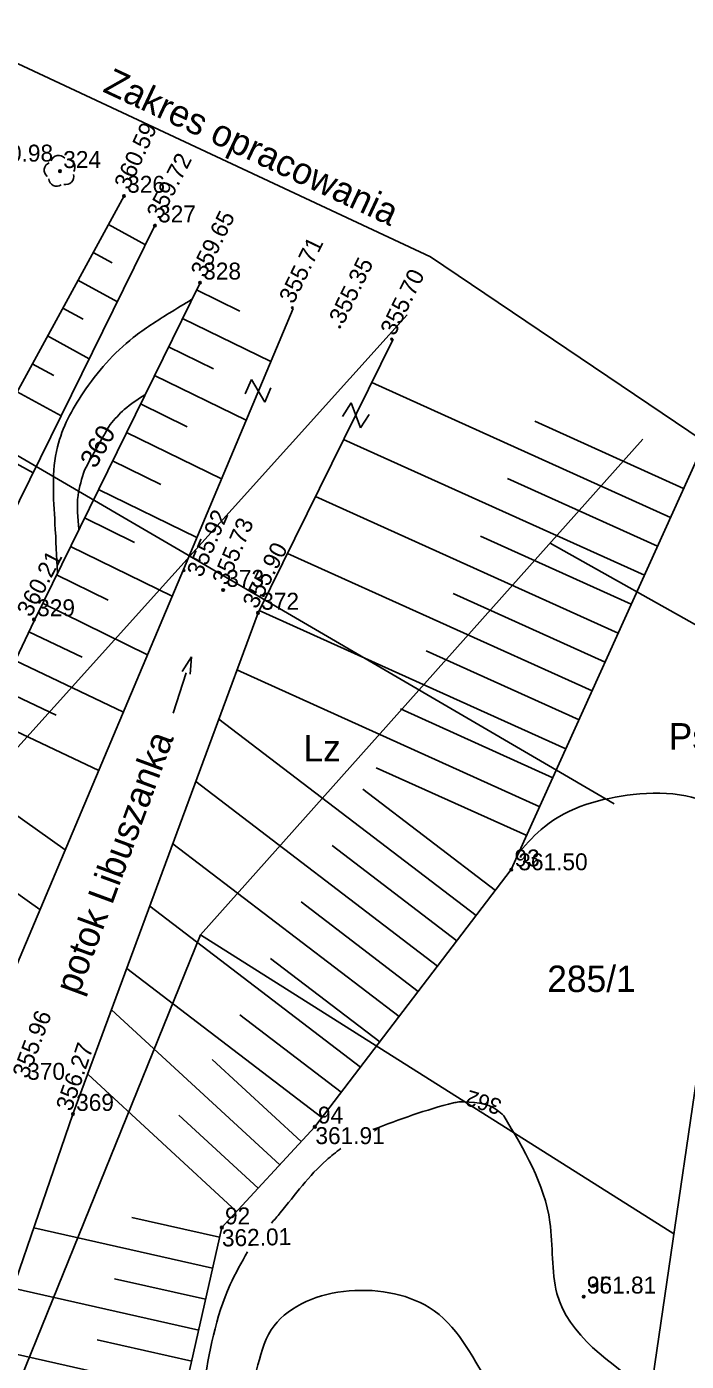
# Model space of a CAD drawing. Extents: x 4635329 to 4651863, y 5356628 to 5367582.
# Drawn here: x 4651765.3 to 4651796.5, y 5357153.9 to 5357217 of the extents above; entities that cross this region are included whole.
import ezdxf

# ---------------------------------------------------------------- set-up
doc = ezdxf.new("R2010")
doc.units = 0
for name, color, linetype in [('Level 1', 7, 'Continuous'), ('Level 12', 7, 'Continuous'), ('Level 2', 7, 'Continuous'), ('Level 4', 7, 'Continuous'), ('Level 44', 7, 'Continuous'), ('Level 45', 7, 'Continuous'), ('Level 46', 7, 'Continuous'), ('Level 47', 7, 'Continuous'), ('Level 48', 7, 'Continuous'), ('Level 5', 7, 'Continuous'), ('Level 50', 7, 'Continuous'), ('Level 51', 7, 'Continuous'), ('Level 53', 7, 'Continuous'), ('Level 55', 7, 'Continuous'), ('Level 6', 7, 'Continuous'), ('Level 63', 7, 'Continuous')]:
    doc.layers.add(name, color=color, linetype=linetype)

msp = doc.modelspace()

# ---------------------------------------------------------------- linework, layer by layer
at = {"layer": 'Level 1'}
for p, q in [((4651784.412, 5357206.105), (4651748.153, 5357223.087)), ((4651801.01, 5357194.891), (4651784.412, 5357206.105)), ((4651790.97, 5357126.195), (4651801.01, 5357194.891))]:
    msp.add_line(p, q, dxfattribs=at)
at = {"layer": 'Level 2'}
msp.add_line((4651793.081, 5357180.253), (4651732.387, 5357215.712), dxfattribs=at)
at = {"layer": 'Level 4'}
for p, q in [((4651783.305, 5357203.355), (4651763.487, 5357181.344)), ((4651773.552, 5357174.065), (4651794.437, 5357197.482)), ((4651790.062, 5357192.577), (4651799.866, 5357187.065)), ((4651762.032, 5357145.618), (4651773.552, 5357174.065)), ((4651773.552, 5357174.065), (4651795.903, 5357159.948))]:
    msp.add_line(p, q, dxfattribs=at)
at = {"layer": 'Level 44'}
for centre in [(4651766.92, 5357210.15), (4651769.94, 5357208.98), (4651771.4, 5357207.58), (4651773.53, 5357204.88), (4651777.887, 5357203.699), (4651780.126, 5357202.792), (4651782.577, 5357202.216), (4651772.775, 5357191.283), (4651774.62, 5357190.36), (4651765.69, 5357188.97), (4651776.27, 5357189.28), (4651788.23, 5357177.15), (4651767.53, 5357165.6), (4651778.95, 5357165), (4651774.56, 5357160.24), (4651791.65, 5357156.97)]:
    msp.add_circle(centre, 0.04, dxfattribs=at)
at = {"layer": 'Level 46'}
for points in [[(4651766.8, 5357191.171), (4651766.68, 5357193.493), (4651766.801, 5357197.132), (4651768.014, 5357199.68), (4651770.379, 5357202.288), (4651772.076, 5357203.44), (4651773.145, 5357204.096)], [(4651770.927, 5357199.578), (4651769.954, 5357198.891), (4651769.289, 5357198.185)], [(4651769.289, 5357198.185), (4651768.681, 5357197.132), (4651768.074, 5357196.024)], [(4651768.074, 5357196.024), (4651767.771, 5357194.827), (4651767.81, 5357193.228)], [(4651788.609, 5357177.988), (4651789.796, 5357179.176), (4651793.983, 5357180.694), (4651796.471, 5357180.633), (4651798.656, 5357180.026), (4651798.832, 5357179.987)], [(4651785.749, 5357166.181), (4651785.506, 5357166.125), (4651781.687, 5357164.864)], [(4651787.87, 5357165.517), (4651787.567, 5357165.791), (4651785.749, 5357166.181)], [(4651794.813, 5357152.488), (4651790.386, 5357157.128), (4651790.053, 5357160.494), (4651787.87, 5357165.517)], [(4651780.184, 5357163.975), (4651779.503, 5357163.426), (4651777.32, 5357160.939), (4651776.898, 5357160.44)], [(4651775.778, 5357159.098), (4651774.955, 5357157.543), (4651773.682, 5357152.641)], [(4651767.905, 5357132.82), (4651768.751, 5357133.654), (4651771.479, 5357136.02), (4651773.238, 5357137.142), (4651775.928, 5357140.766), (4651776.686, 5357143.374), (4651776.959, 5357145.861), (4651775.928, 5357148.651), (4651775.746, 5357151.41), (4651776.201, 5357153.503), (4651776.895, 5357155.4), (4651784.353, 5357156.461), (4651787.142, 5357152.883), (4651788.991, 5357150.517), (4651791.083, 5357149.092), (4651794.095, 5357147.575)]]:
    msp.add_spline(points, degree=3, dxfattribs=at)
at = {"layer": 'Level 48'}
for p, q in [((4651769.204, 5357207.631), (4651770.954, 5357206.675)), ((4651768.485, 5357206.314), (4651769.388, 5357205.821)), ((4651767.767, 5357204.997), (4651769.627, 5357203.982)), ((4651773.365, 5357204.543), (4651775.409, 5357203.539)), ((4651767.048, 5357203.681), (4651768.006, 5357203.158)), ((4651772.704, 5357203.196), (4651776.872, 5357201.15)), ((4651766.33, 5357202.364), (4651768.3, 5357201.289)), ((4651772.042, 5357201.85), (4651774.167, 5357200.807)), ((4651765.611, 5357201.047), (4651766.624, 5357200.495)), ((4651771.381, 5357200.503), (4651775.71, 5357198.378)), ((4651764.892, 5357199.73), (4651766.973, 5357198.595)), ((4651795.75, 5357193.794), (4651781.638, 5357200.17)), ((4651770.72, 5357199.157), (4651772.925, 5357198.075)), ((4651796.367, 5357195.161), (4651789.334, 5357198.339)), ((4651770.059, 5357197.81), (4651774.548, 5357195.607)), ((4651794.515, 5357191.06), (4651780.311, 5357197.477)), ((4651763.455, 5357197.097), (4651765.645, 5357195.902)), ((4651769.398, 5357196.464), (4651771.683, 5357195.343)), ((4651795.132, 5357192.427), (4651788.053, 5357195.625)), ((4651768.737, 5357195.117), (4651773.386, 5357192.836)), ((4651793.279, 5357188.326), (4651778.984, 5357194.785)), ((4651768.076, 5357193.771), (4651770.44, 5357192.61)), ((4651793.897, 5357189.693), (4651786.772, 5357192.912)), ((4651767.415, 5357192.424), (4651772.221, 5357190.065)), ((4651792.044, 5357185.592), (4651777.657, 5357192.093)), ((4651766.754, 5357191.078), (4651769.195, 5357189.88)), ((4651766.093, 5357189.732), (4651771.052, 5357187.297)), ((4651792.662, 5357186.959), (4651785.491, 5357190.199)), ((4651790.809, 5357182.858), (4651776.33, 5357189.4)), ((4651765.439, 5357188.382), (4651767.967, 5357187.18)), ((4651791.427, 5357184.225), (4651784.21, 5357187.486)), ((4651764.795, 5357187.027), (4651769.912, 5357184.596)), ((4651789.574, 5357180.124), (4651775.275, 5357186.585)), ((4651764.152, 5357185.672), (4651766.74, 5357184.442)), ((4651790.191, 5357181.491), (4651782.994, 5357184.743)), ((4651763.508, 5357184.317), (4651768.744, 5357181.829)), ((4651786.569, 5357174.976), (4651774.416, 5357184.258)), ((4651761.916, 5357181.785), (4651767.165, 5357178.088)), ((4651788.956, 5357178.758), (4651781.855, 5357181.966)), ((4651784.748, 5357172.592), (4651773.329, 5357181.313)), ((4651787.48, 5357176.168), (4651781.22, 5357180.949)), ((4651760.189, 5357179.333), (4651765.971, 5357175.26)), ((4651782.927, 5357170.207), (4651772.243, 5357178.368)), ((4651785.659, 5357173.784), (4651779.766, 5357178.285)), ((4651781.106, 5357167.823), (4651771.156, 5357175.423)), ((4651783.838, 5357171.399), (4651778.312, 5357175.62)), ((4651782.017, 5357169.015), (4651776.858, 5357172.956)), ((4651779.285, 5357165.439), (4651770.069, 5357172.479)), ((4651777.291, 5357163.201), (4651769.348, 5357170.526)), ((4651780.196, 5357166.631), (4651775.404, 5357170.291)), ((4651778.308, 5357164.304), (4651774.109, 5357168.176)), ((4651775.257, 5357160.996), (4651768.225, 5357167.481)), ((4651776.274, 5357162.098), (4651772.53, 5357165.551)), ((4651774.456, 5357159.779), (4651770.313, 5357160.713)), ((4651774.126, 5357158.316), (4651765.678, 5357160.22)), ((4651773.796, 5357156.853), (4651769.492, 5357157.823)), ((4651773.467, 5357155.39), (4651764.696, 5357157.367)), ((4651773.137, 5357153.926), (4651768.671, 5357154.933)), ((4651772.807, 5357152.463), (4651763.714, 5357154.513))]:
    msp.add_line(p, q, dxfattribs=at)
for points in [[(4651756.27, 5357183.93), (4651769.94, 5357208.98)], [(4651771.4, 5357207.58), (4651762.54, 5357189.6), (4651756.27, 5357183.93)], [(4651742.61, 5357155.07), (4651748.7, 5357162.32), (4651754.89, 5357171.81), (4651763.11, 5357183.48), (4651765.69, 5357188.91), (4651773.53, 5357204.88)], [(4651788.23, 5357177.15), (4651796.985, 5357196.528)], [(4651788.23, 5357177.15), (4651778.95, 5357165), (4651774.56, 5357160.24), (4651772.52, 5357151.19), (4651770.34, 5357137.07), (4651766.1, 5357132.52), (4651760.1, 5357122.43), (4651755.24, 5357116.54), (4651754.43, 5357111.05), (4651754.06, 5357101.72), (4651764.92, 5357096.97)]]:
    msp.add_lwpolyline(points, dxfattribs=at)
at = {"layer": 'Level 50'}
for p, q in [((4651772.754, 5357191.33), (4651777.929, 5357203.669)), ((4651776.27, 5357189.28), (4651782.647, 5357202.217)), ((4651772.754, 5357191.33), (4651762.59, 5357167.25)), ((4651767.53, 5357165.6), (4651776.27, 5357189.28)), ((4651772.689, 5357186.507), (4651773.129, 5357187.205)), ((4651773.129, 5357187.205), (4651773.069, 5357186.382)), ((4651772.254, 5357184.545), (4651772.879, 5357186.445)), ((4651760.04, 5357143.84), (4651767.53, 5357165.6))]:
    msp.add_line(p, q, dxfattribs=at)
at = {"layer": 'Level 53'}
for p, q in [((4651775.961, 5357200.312), (4651775.666, 5357199.623)), ((4651776.585, 5357199.229), (4651775.961, 5357200.312)), ((4651776.881, 5357199.918), (4651776.585, 5357199.229)), ((4651780.669, 5357199.198), (4651780.265, 5357198.565)), ((4651781.109, 5357198.028), (4651780.669, 5357199.198)), ((4651781.512, 5357198.66), (4651781.109, 5357198.028))]:
    msp.add_line(p, q, dxfattribs=at)
at = {"layer": 'Level 55'}
msp.add_circle((4651766.92, 5357210.15), 0.045, dxfattribs=at)
for centre, start, end in [((4651766.549, 5357210.2), 112.43885, 232.09024), ((4651766.853, 5357210.519), 40.34881, 160.13059), ((4651767.25, 5357210.328), 328.34804, 88.13199), ((4651767.191, 5357209.891), 256.39056, 16.04195), ((4651766.757, 5357209.812), 184.38753, 304.09327)]:
    msp.add_arc(centre, 0.375, start, end, dxfattribs=at)
at = {"layer": 'Level 63'}
for centre in [(4651766.92, 5357210.15), (4651769.94, 5357208.98), (4651771.4, 5357207.58), (4651773.53, 5357204.88), (4651774.62, 5357190.36), (4651765.69, 5357188.97), (4651776.27, 5357189.28), (4651788.23, 5357177.15), (4651767.53, 5357165.6), (4651778.95, 5357165), (4651774.56, 5357160.24), (4651791.65, 5357156.97)]:
    msp.add_circle(centre, 0.06, dxfattribs=at)

# ---------------------------------------------------------------- texts
at = {"layer": 'Level 12'}
for s, p in [('Ps', (4651795.66, 5357182.821)), ('Lz', (4651778.413, 5357182.261))]:
    msp.add_text(s, height=1.25, dxfattribs=at).set_placement(p)
at = {"layer": 'Level 45'}
for s, rotation, p in [('360.59', 65.61012, (4651770.168, 5357209.228)), ('359.72', 62.71454, (4651771.673, 5357207.822)), ('359.65', 63.95047, (4651773.765, 5357205.078)), ('355.71', 63.95047, (4651777.94, 5357203.837)), ('355.35', 63.95047, (4651780.3, 5357202.869)), ('355.70', 63.95047, (4651782.721, 5357202.324)), ('355.92', 66.98682, (4651773.609, 5357190.916)), ('355.73', 66.98682, (4651774.804, 5357190.537)), ('355.90', 62.92249, (4651776.204, 5357189.423)), ('360.21', 62.49045, (4651765.542, 5357189.039)), ('355.96', 69.49742, (4651765.393, 5357167.237)), ('356.27', 71.09956, (4651767.457, 5357165.692)), ('362.01', 1.33329, (4651774.572, 5357159.341))]:
    msp.add_text(s, height=0.8, rotation=rotation, dxfattribs=at).set_placement(p)
for s, p in [('360.98', (4651763.319, 5357210.603)), ('361.50', (4651788.562, 5357177.119)), ('361.91', (4651778.979, 5357164.181)), ('361.81', (4651791.8, 5357157.12))]:
    msp.add_text(s, height=0.8, dxfattribs=at).set_placement(p)
at = {"layer": 'Level 47'}
for s, height, rotation, p in [('360', 0.9, 60.67872, (4651768.595, 5357196.06)), ('362', 0.75, 163.20612, (4651787.829, 5357166.268))]:
    msp.add_text(s, height=height, rotation=rotation, dxfattribs=at).set_placement(p)
at = {"layer": 'Level 5'}
msp.add_text('285/1', height=1.25, dxfattribs=at).set_placement((4651789.925, 5357171.366))
at = {"layer": 'Level 51'}
msp.add_text('potok Libuszanka', height=1.25, rotation=69.74151, dxfattribs=at).set_placement((4651767.797, 5357171.174))
at = {"layer": 'Level 6'}
msp.add_text('Zakres opracowania', height=1.25, rotation=334.90383, dxfattribs=at).set_placement((4651768.889, 5357213.927))
at = {"layer": 'Level 63'}
for s, p in [('324', (4651767.07, 5357210.3)), ('326', (4651770.09, 5357209.13)), ('327', (4651771.55, 5357207.73)), ('328', (4651773.68, 5357205.03)), ('373', (4651774.77, 5357190.51)), ('329', (4651765.84, 5357189.12)), ('372', (4651776.42, 5357189.43)), ('93', (4651788.38, 5357177.3)), ('370', (4651765.37, 5357167.22)), ('369', (4651767.68, 5357165.75)), ('94', (4651779.1, 5357165.15)), ('92', (4651774.71, 5357160.39)), ('95', (4651791.8, 5357157.12))]:
    msp.add_text(s, height=0.8, dxfattribs=at).set_placement(p)

doc.saveas('drawing.dxf')
